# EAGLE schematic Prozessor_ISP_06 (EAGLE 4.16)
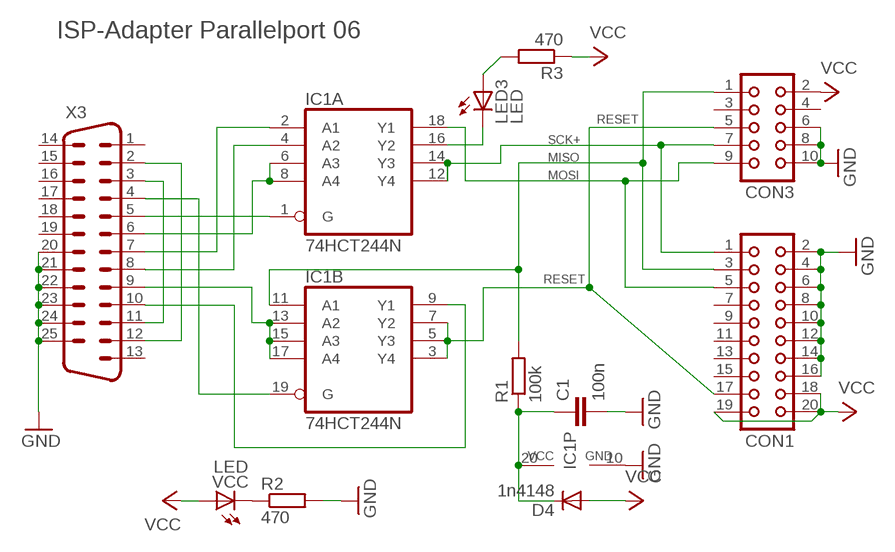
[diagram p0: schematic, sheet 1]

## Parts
C1  100n  C-EU075-032X103  [C075-032X103]
CON1  CON20  [CON20]
CON3  CON10  [CON10]
D4  1n4148  DIODE-DO35-10  [DO35-10]
IC1  74HCT244N  [DIL20]
LED3  LED  LED3MM  [LED3MM]
R1  100k  R-EU_0204/7  [0204/7]
R2  470  R-EU_0204/7  [0204/7]
R3  470  R-EU_0207/12  [0207/12]
VCC  LED  LED3MM  [LED3MM]
X3  M25HP  [M25HP]

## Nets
GND: C1.2 CON1.2 CON1.4 CON1.6 CON1.8 CON1.10 CON1.12 CON1.14 CON1.16 CON3.6 CON3.8 CON3.10 IC1.10(P:GND) R2.2 X3.20 X3.21 X3.22 X3.23 X3.24 X3.25
N$2: LED3.A R3.2
N$4: R2.1 VCC.K(C)
N$17: IC1.2(A:A1) X3.7
N$19: IC1.4(A:A2) X3.8
N$20: IC1.6(A:A3) IC1.8(A:A4) X3.6
N$21: IC1.1(A:G) X3.5
N$22: IC1.13(B:A2) IC1.15(B:A3) IC1.17(B:A4) X3.9
N$23: IC1.9(B:Y1) X3.10
N$24: IC1.19(B:G) X3.4
N$25: X3.3 X3.11
N$26: X3.2 X3.12
N$28: C1.1 D4.C IC1.20(P:VCC) R1.1
N$32: IC1.16(A:Y2) LED3.K(C)
PB5-MOSI: CON1.5 CON3.9 IC1.18(A:Y1)
PB6-MISO: CON1.3 CON3.1 IC1.11(B:A1) R1.2
PB7-SCK: CON1.1 CON3.7 IC1.12(A:Y4) IC1.14(A:Y3)
RESET: CON1.17 CON3.5 IC1.3(B:Y4) IC1.5(B:Y3) IC1.7(B:Y2)
VCC: CON1.18 CON1.19 CON1.20 CON3.2 D4.A R3.1 VCC.A
Unconnected: CON1.7 CON1.9 CON1.11 CON1.13 CON1.15 CON3.3 CON3.4 X3.1 X3.13 X3.14 X3.15 X3.16 X3.17 X3.18 X3.19

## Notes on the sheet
- ISP-Adapter Parallelport 06
- RESET
- SCK+
- MISO
- MOSI
- RESET

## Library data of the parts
C1 = rcl:C-EU: CAPACITOR, European symbol
CON1 = con-harting:CON20: CONNECTOR
CON3 = con-harting:CON10: CONNECTOR
D4 = diode:DIODE-: DIODE
IC1 = 74xx-eu:74*244: Octal BUFFER and LINE DRIVER, 3-state
LED3 VCC = led:LED: LED
R1-R3 = rcl:R-EU_: RESISTOR, European symbol
X3 = con-subd:M25: SUB-D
